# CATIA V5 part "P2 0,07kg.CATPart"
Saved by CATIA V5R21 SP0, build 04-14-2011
Part number: Part2
Material "Aluminium": density 2710 kg/m3, Young's modulus 7e+10 Pa, Poisson ratio 0.346, thermal expansion 2.36e-05 1/K
Bounding box of the stored display mesh (mm): x -12 to 12, y -52.938 to 27.062, z -10.709 to 13.291
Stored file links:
  C:\Users\HP\Desktop\Mes Fichiers\catia lesson\Mini Projet\Projet 1\P2 0,07kg.CATPart
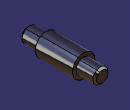
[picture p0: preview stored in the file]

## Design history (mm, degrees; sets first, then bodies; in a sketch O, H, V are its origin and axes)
AxisSystem1: origin (0, 0, 0), X (1, 0, 0), Y (0, 1, 0), Z (0, 0, 1)
Body1 (main body), material "Aluminium"
  Sketch1 on YZ plane of AxisSystem1, origin (0, 0, 0), H (0, 1, 0), V (0, 0, 1)
    line L1 (-52.9377, 9.2915) -> (-32.9377, 9.2915)
    line L2 (-32.9377, 9.2915) -> (-32.9377, 13.2915)
    line L3 (-32.9377, 13.2915) -> (7.0623, 13.2915)
    line L4 (7.0623, 13.2915) -> (7.0623, 9.2915)
    point P5 (7.0623, 9.2915)
    line L5 (7.0623, 9.2915) -> (27.0623, 9.2915)
    line L6 (27.0623, 9.2915) -> (27.0623, 1.2915)
    line L7 (27.0623, 1.2915) -> (-52.9377, 1.2915)
    line L8 (-52.9377, 1.2915) -> (-52.9377, 9.2915)
    axis line L9 (-89.8301, 1.2915) -> (45.3143, 1.2915)
    point P9 (-89.8301, 1.2915)
    length L7 = 80
    length L3 = 40
    length L1 = 20
    distance L3 L9 = 12
    distance L1 L9 = 8
    horizontal: L1 H, L3 H, L5 H, L7 H, L9 H
    vertical: L2 V, L4 V, L6 V, L8 V
    coincidence: P5 L1, P9 L7
  Shaft1: profile Sketch1, axis Sketch1.L9, angle 360
  Chamfer1: length 2, angle 45, on edge [face of Shaft1 from Sketch1.L5 | face of Shaft1 from Sketch1.L6]; edge [face of Shaft1 from Sketch1.L8 | face of Shaft1 from Sketch1.L1]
